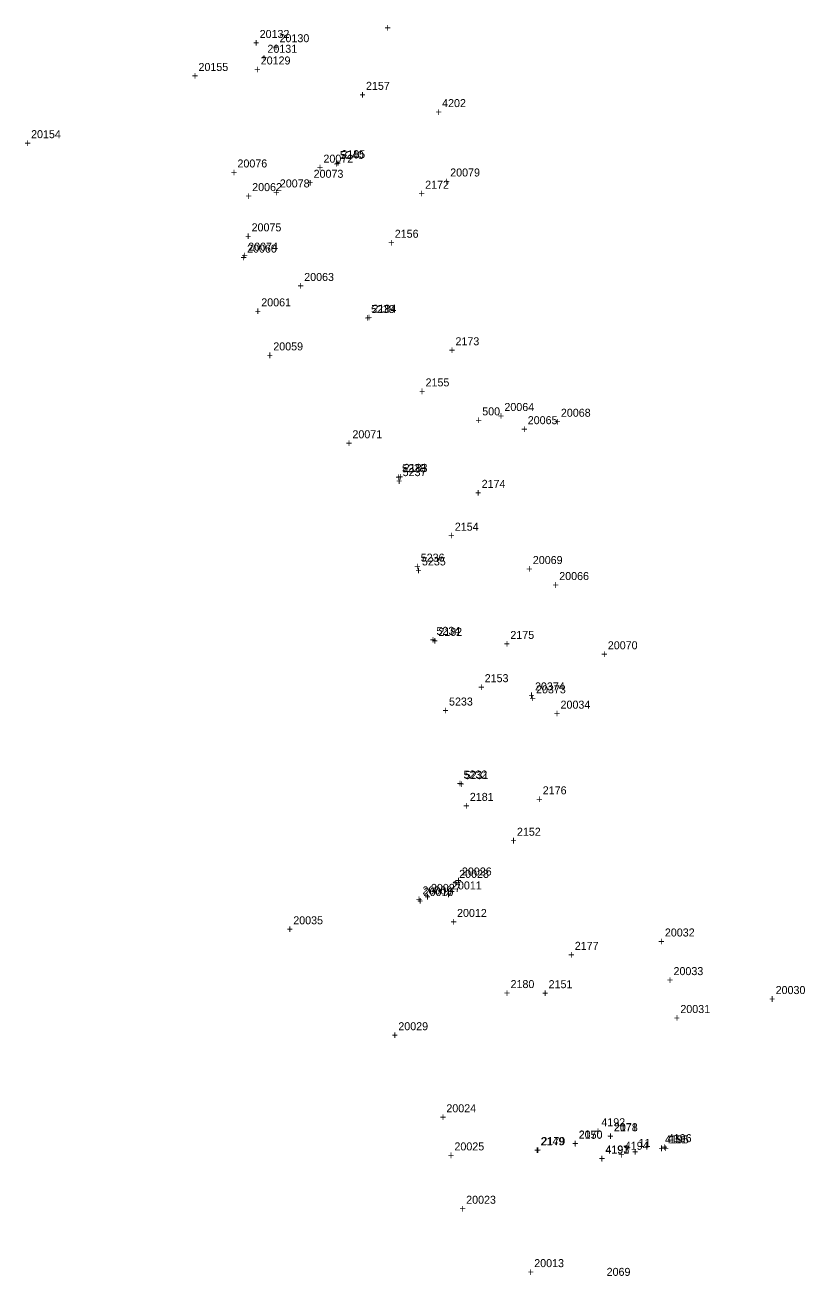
# Model space of a CAD drawing. Extents: x 1036751 to 1042192, y 772604 to 785439.
# Drawn here: x 1041470.9 to 1041714.7, y 773812.1 to 774202.9 of the extents above; entities that cross this region are included whole.
import ezdxf

# ---------------------------------------------------------------- set-up
doc = ezdxf.new("R2010")
doc.units = 0
for name, color, linetype in [('S_Buildings', 7, 'Continuous'), ('S_Buildings_SillElevation', 7, 'Continuous'), ('S_Control_Geodetic_ControlPoint', 7, 'Continuous'), ('S_Control_Temp_Traverse', 7, 'Continuous'), ('S_Control_Traverse_Point', 7, 'Continuous'), ('S_Curb_Type_2', 7, 'Continuous'), ('S_Drainage_DrainOutlet', 7, 'Continuous'), ('S_Fencing_Picket', 7, 'Continuous'), ('S_Fencing_StockadePostPlank', 7, 'Continuous'), ('S_Property_IronPipeFound', 7, 'Continuous'), ('S_Property_StoneWall', 7, 'Continuous'), ('S_Roadway_Centerline', 7, 'Continuous'), ('S_Roadway_Edge_Pavement', 7, 'Continuous'), ('S_Roadway_Monument', 7, 'Continuous'), ('S_Traffic_Sign_SinglePost', 7, 'Continuous'), ('S_Trees_Conifer_Pay', 7, 'Continuous'), ('S_Trees_Decid_Pay', 7, 'Continuous'), ('S_Trees_Root', 7, 'Continuous'), ('S_Utilities_GuyWire3', 7, 'Continuous'), ('S_Utilities_Hydrant', 7, 'Continuous'), ('S_Utilities_Pole_Power', 7, 'Continuous'), ('S_Utilities_UG_Electrical_Line', 7, 'Continuous'), ('S_Utilities_UG_Sanitary_MH', 7, 'Continuous'), ('S_Utilities_UG_Sanitary_Sewer', 7, 'Continuous'), ('S_Utilities_UG_Water_Line', 7, 'Continuous')]:
    doc.layers.add(name, color=color, linetype=linetype)

msp = doc.modelspace()

# ---------------------------------------------------------------- texts
at = {"layer": 'S_Buildings'}
for s, p in [('20060', (1041540.35, 774131.82)), ('+', (1041538.29, 774129.07)), ('20059', (1041548.54, 774101.27)), ('+', (1041546.48, 774098.52)), ('20065', (1041628.06, 774078.21)), ('+', (1041626, 774075.46)), ('20066', (1041637.9, 774029.51)), ('+', (1041635.84, 774026.76)), ('+', (1041668.86, 773915.39)), ('20032', (1041670.92, 773918.14)), ('20030', (1041705.54, 773900.15)), ('+', (1041703.48, 773897.4)), ('20031', (1041675.76, 773894.22)), ('+', (1041673.7, 773891.47)), ('20024', (1041602.63, 773863.21)), ('+', (1041600.57, 773860.46)), ('20023', (1041608.82, 773834.63)), ('+', (1041606.76, 773831.88))]:
    msp.add_text(s, height=2.5, dxfattribs=at).set_placement(p)
at = {"layer": 'S_Buildings_SillElevation'}
for s, p in [('20061', (1041544.78, 774115.03)), ('+', (1041542.72, 774112.28)), ('20068', (1041638.42, 774080.53)), ('+', (1041636.36, 774077.78)), ('20033', (1041673.62, 773906.07)), ('+', (1041671.56, 773903.32)), ('20025', (1041605.15, 773851.3)), ('+', (1041603.09, 773848.55))]:
    msp.add_text(s, height=2.5, dxfattribs=at).set_placement(p)
at = {"layer": 'S_Control_Geodetic_ControlPoint'}
for s, p in [('11', (1041662.73, 773852.41)), ('11', (1041662.73, 773852.41)), ('11', (1041662.73, 773852.41)), ('11', (1041662.73, 773852.41)), ('11', (1041662.73, 773852.41)), ('11', (1041662.73, 773852.41)), ('11', (1041662.73, 773852.41)), ('11', (1041662.73, 773852.41)), ('11', (1041662.73, 773852.41)), ('11', (1041662.73, 773852.41)), ('+', (1041660.67, 773849.66)), ('+', (1041660.67, 773849.66)), ('+', (1041660.67, 773849.66)), ('+', (1041660.67, 773849.66)), ('+', (1041660.67, 773849.66)), ('+', (1041660.67, 773849.66)), ('+', (1041660.67, 773849.66)), ('+', (1041660.67, 773849.66)), ('+', (1041660.67, 773849.66)), ('+', (1041660.67, 773849.66))]:
    msp.add_text(s, height=2.5, dxfattribs=at).set_placement(p)
at = {"layer": 'S_Control_Temp_Traverse'}
for s, p in [('151', (1041672.25, 773853.5)), ('+', (1041670.19, 773850.75))]:
    msp.add_text(s, height=2.5, dxfattribs=at).set_placement(p)
at = {"layer": 'S_Control_Traverse_Point'}
for s, p in [('500', (1041613.83, 774080.97)), ('500', (1041613.83, 774080.97)), ('500', (1041613.83, 774080.97)), ('500', (1041613.83, 774080.97)), ('500', (1041613.83, 774080.97)), ('500', (1041613.83, 774080.97)), ('500', (1041613.83, 774080.97)), ('500', (1041613.83, 774080.97)), ('+', (1041611.77, 774078.22)), ('+', (1041611.77, 774078.22)), ('+', (1041611.77, 774078.22)), ('+', (1041611.77, 774078.22)), ('+', (1041611.77, 774078.22)), ('+', (1041611.77, 774078.22)), ('+', (1041611.77, 774078.22)), ('+', (1041611.77, 774078.22))]:
    msp.add_text(s, height=2.5, dxfattribs=at).set_placement(p)
at = {"layer": 'S_Curb_Type_2'}
for s, p in [('+', (1041567.3, 774158.31)), ('5240', (1041569.36, 774161.06)), ('5239', (1041579.09, 774112.94)), ('+', (1041577.03, 774110.19)), ('+', (1041586.71, 774060.47)), ('5238', (1041588.77, 774063.22)), ('5237', (1041588.97, 774061.98)), ('+', (1041586.91, 774059.23)), ('5236', (1041594.61, 774035.26)), ('5235', (1041595, 774034.08)), ('+', (1041592.55, 774032.51)), ('+', (1041592.94, 774031.33)), ('+', (1041597.47, 774009.64)), ('5234', (1041599.53, 774012.39)), ('5233', (1041603.46, 773990.3)), ('+', (1041601.4, 773987.55)), ('5232', (1041607.97, 773967.5)), ('5231', (1041608.36, 773967.31)), ('+', (1041605.91, 773964.75)), ('+', (1041606.3, 773964.56))]:
    msp.add_text(s, height=2.5, dxfattribs=at).set_placement(p)
at = {"layer": 'S_Drainage_DrainOutlet'}
for s, p in [('20073', (1041561.14, 774155.2)), ('+', (1041559.08, 774152.45))]:
    msp.add_text(s, height=2.5, dxfattribs=at).set_placement(p)
at = {"layer": 'S_Fencing_Picket'}
for s, p in [('20010', (1041595.52, 773930.78)), ('20011', (1041604.39, 773932.85)), ('+', (1041593.46, 773928.03)), ('+', (1041602.33, 773930.1)), ('20012', (1041605.97, 773924.24)), ('+', (1041603.91, 773921.49)), ('20013', (1041630.09, 773814.83)), ('+', (1041628.03, 773812.08))]:
    msp.add_text(s, height=2.5, dxfattribs=at).set_placement(p)
at = {"layer": 'S_Fencing_StockadePostPlank'}
for s, p in [('20155', (1041525.16, 774188.58)), ('+', (1041523.1, 774185.83)), ('20154', (1041472.84, 774167.58)), ('+', (1041470.78, 774164.83)), ('20076', (1041537.34, 774158.43)), ('+', (1041535.28, 774155.68)), ('20075', (1041541.76, 774138.47)), ('+', (1041539.7, 774135.72)), ('20074', (1041540.68, 774132.43)), ('+', (1041538.62, 774129.68))]:
    msp.add_text(s, height=2.5, dxfattribs=at).set_placement(p)
at = {"layer": 'S_Property_IronPipeFound'}
for s, p in [('4202', (1041601.3, 774177.29)), ('+', (1041599.24, 774174.54)), ('20009', (1041595.17, 773931.29)), ('+', (1041593.11, 773928.55)), ('20035', (1041554.78, 773921.95)), ('+', (1041552.72, 773919.2))]:
    msp.add_text(s, height=2.5, dxfattribs=at).set_placement(p)
at = {"layer": 'S_Property_StoneWall'}
for s, p in [('20078', (1041550.58, 774152.19)), ('+', (1041548.52, 774149.44))]:
    msp.add_text(s, height=2.5, dxfattribs=at).set_placement(p)
at = {"layer": 'S_Roadway_Centerline'}
for s, p in [('2157', (1041577.51, 774182.68)), ('+', (1041575.45, 774179.93)), ('2156', (1041586.5, 774136.46)), ('+', (1041584.44, 774133.71)), ('2155', (1041596.13, 774090.02)), ('+', (1041594.07, 774087.27)), ('2154', (1041605.27, 774044.93)), ('+', (1041603.21, 774042.18)), ('2153', (1041614.61, 773997.6)), ('+', (1041612.55, 773994.85)), ('+', (1041622.62, 773946.87)), ('2152', (1041624.68, 773949.62)), ('2151', (1041634.58, 773901.99)), ('+', (1041632.52, 773899.24)), ('2070', (1041643.98, 773855.02)), ('2150', (1041644, 773854.93)), ('+', (1041641.91, 773852.27)), ('+', (1041641.94, 773852.18)), ('2069', (1041652.72, 773812.1))]:
    msp.add_text(s, height=2.5, dxfattribs=at).set_placement(p)
at = {"layer": 'S_Roadway_Edge_Pavement'}
for s, p in [('+', (1041583.29, 774200.84)), ('2185', (1041569.81, 774161.32)), ('+', (1041567.75, 774158.57)), ('2172', (1041596.01, 774151.79)), ('+', (1041593.95, 774149.04)), ('2184', (1041579.52, 774113.05)), ('+', (1041577.46, 774110.3)), ('2173', (1041605.48, 774102.87)), ('+', (1041603.42, 774100.12)), ('+', (1041587.23, 774060.56)), ('2183', (1041589.29, 774063.31)), ('2174', (1041613.66, 774058.32)), ('+', (1041611.6, 774055.57)), ('+', (1041598.05, 774009.33)), ('2182', (1041600.11, 774012.08)), ('2175', (1041622.63, 774011.11)), ('+', (1041620.57, 774008.36)), ('2176', (1041632.75, 773962.56)), ('2181', (1041609.96, 773960.51)), ('+', (1041630.69, 773959.81)), ('+', (1041607.9, 773957.76)), ('2177', (1041642.76, 773913.97)), ('+', (1041640.7, 773911.22)), ('2180', (1041622.69, 773902.02)), ('+', (1041620.63, 773899.27)), ('2071', (1041654.97, 773857.32)), ('2178', (1041655, 773857.27)), ('2149', (1041632.08, 773852.91)), ('2179', (1041632.33, 773852.95)), ('+', (1041652.91, 773854.57)), ('+', (1041652.94, 773854.52)), ('+', (1041630.02, 773850.16)), ('+', (1041630.26, 773850.2))]:
    msp.add_text(s, height=2.5, dxfattribs=at).set_placement(p)
at = {"layer": 'S_Roadway_Monument'}
for s, p in [('20129', (1041544.61, 774190.61)), ('+', (1041542.55, 774187.86))]:
    msp.add_text(s, height=2.5, dxfattribs=at).set_placement(p)
at = {"layer": 'S_Traffic_Sign_SinglePost'}
for s, p in [('20079', (1041603.83, 774155.61)), ('+', (1041601.77, 774152.86)), ('20034', (1041638.31, 773989.32)), ('+', (1041636.25, 773986.57))]:
    msp.add_text(s, height=2.5, dxfattribs=at).set_placement(p)
at = {"layer": 'S_Trees_Conifer_Pay'}
for s, p in [('20069', (1041629.65, 774034.51)), ('+', (1041627.59, 774031.76))]:
    msp.add_text(s, height=2.5, dxfattribs=at).set_placement(p)
at = {"layer": 'S_Trees_Decid_Pay'}
for s, p in [('20132', (1041544.28, 774198.89)), ('+', (1041542.21, 774196.14)), ('20131', (1041546.7, 774194.26)), ('+', (1041544.64, 774191.51)), ('20062', (1041541.94, 774151.04)), ('+', (1041539.88, 774148.29)), ('20063', (1041558.2, 774122.96)), ('+', (1041556.14, 774120.21)), ('+', (1041618.71, 774079.58)), ('20064', (1041620.77, 774082.33)), ('20071', (1041573.27, 774073.81)), ('+', (1041571.21, 774071.06))]:
    msp.add_text(s, height=2.5, dxfattribs=at).set_placement(p)
at = {"layer": 'S_Trees_Root'}
for s, p in [('20130', (1041550.49, 774197.56)), ('+', (1041548.43, 774194.81))]:
    msp.add_text(s, height=2.5, dxfattribs=at).set_placement(p)
at = {"layer": 'S_Utilities_GuyWire3'}
for s, p in [('20027', (1041597.81, 773932.07)), ('+', (1041595.75, 773929.32))]:
    msp.add_text(s, height=2.5, dxfattribs=at).set_placement(p)
at = {"layer": 'S_Utilities_Hydrant'}
for s, p in [('4196', (1041671.83, 773853.88)), ('+', (1041669.77, 773851.13))]:
    msp.add_text(s, height=2.5, dxfattribs=at).set_placement(p)
at = {"layer": 'S_Utilities_Pole_Power'}
for s, p in [('20072', (1041564.21, 774159.92)), ('+', (1041562.15, 774157.17)), ('20070', (1041653.09, 774007.88)), ('+', (1041651.03, 774005.13)), ('20026', (1041607.49, 773937.2)), ('+', (1041605.43, 773934.45))]:
    msp.add_text(s, height=2.5, dxfattribs=at).set_placement(p)
at = {"layer": 'S_Utilities_UG_Electrical_Line'}
for s, p in [('20028', (1041606.63, 773936.46)), ('+', (1041604.57, 773933.71)), ('20029', (1041587.62, 773888.85)), ('+', (1041585.56, 773886.1))]:
    msp.add_text(s, height=2.5, dxfattribs=at).set_placement(p)
at = {"layer": 'S_Utilities_UG_Sanitary_MH'}
for s, p in [('20374', (1041630.33, 773995.03)), ('+', (1041628.27, 773992.28))]:
    msp.add_text(s, height=2.5, dxfattribs=at).set_placement(p)
at = {"layer": 'S_Utilities_UG_Sanitary_Sewer'}
for s, p in [('20373', (1041630.66, 773994.11)), ('+', (1041628.6, 773991.36))]:
    msp.add_text(s, height=2.5, dxfattribs=at).set_placement(p)
at = {"layer": 'S_Utilities_UG_Water_Line'}
for s, p in [('4192', (1041651.07, 773858.85)), ('+', (1041649.01, 773856.1)), ('4195', (1041670.94, 773853.49)), ('4191', (1041652.29, 773850.31)), ('4197', (1041652.34, 773850.25)), ('4193', (1041652.37, 773850.35)), ('4194', (1041658.39, 773851.49)), ('+', (1041668.88, 773850.74)), ('+', (1041650.23, 773847.56)), ('+', (1041650.28, 773847.5)), ('+', (1041650.31, 773847.6)), ('+', (1041656.33, 773848.74))]:
    msp.add_text(s, height=2.5, dxfattribs=at).set_placement(p)

doc.saveas('drawing.dxf')
